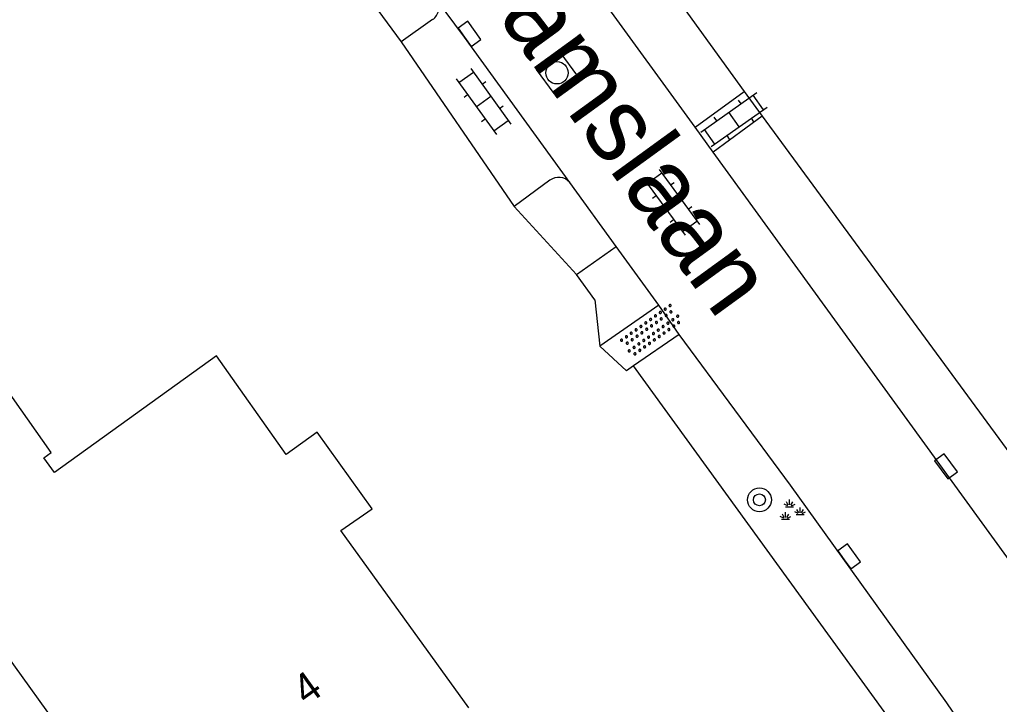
# Model space of a CAD drawing. Extents: x 136000 to 138005, y 398500 to 400500.
# Drawn here: x 137882.54 to 137915.41, y 398783.52 to 398806.52 of the extents above; entities that cross this region are included whole.
import ezdxf

# ---------------------------------------------------------------- set-up
doc = ezdxf.new("R2010")
doc.units = 0
for name, color, linetype in [('gg-afsc-erfafscheiding', 7, 'Continuous'), ('gg-anno-huisnummerreeks BGT', 7, 'Continuous'), ('gg-anno-openbare ruimte label', 7, 'Continuous'), ('gg-bbg-gedigitaliseerde bebouwing', 7, 'Continuous'), ('gg-bbg-hoofdgebouw', 7, 'Continuous'), ('gg-knt-verharding', 7, 'Continuous'), ('gt-grn-vlakafsluiter', 7, 'Continuous'), ('gt-symb-boom', 7, 'Continuous'), ('gt-symb-groenvak', 7, 'Continuous'), ('gt-symb-klinker verharding', 7, 'Continuous'), ('gt-symb-kolk', 7, 'Continuous'), ('gt-symb-overige verharding', 7, 'Continuous'), ('gt-symb-rioolschacht', 7, 'Continuous')]:
    doc.layers.add(name, color=color, linetype=linetype)

# ---------------------------------------------------------------- blocks, each defined once
blk = doc.blocks.new('gt0-KL1')
at = {"layer": 'gt-symb-klinker verharding'}
for p, q in [((-0.5, 0.3), (-0.5, 0.45)), ((0.5, 0.3), (0.5, 0.45)), ((-1.15, 0.3), (1.15, 0.3)), ((-1, -0.3), (-1, 0.3)), ((0, -0.3), (0, 0.3)), ((1, -0.3), (1, 0.3)), ((-1.15, -0.3), (1.15, -0.3)), ((-0.5, -0.45), (-0.5, -0.3)), ((0.5, -0.45), (0.5, -0.3))]:
    blk.add_line(p, q, dxfattribs=at)
blk = doc.blocks.new('gt0-BOOM')
at = {"layer": 'gt-symb-boom'}
for radius in [0.4, 0.2]:
    blk.add_circle((0, 0), radius, dxfattribs=at)
blk = doc.blocks.new('gt0-GRVAK')
at = {"layer": 'gt-symb-groenvak'}
for p, q in [((-0.047, 0.214), (-0.047, 0.393)), ((-0.11, 0.189), (-0.228, 0.24)), ((-0.182, 0.153), (0.088, 0.153)), ((-0.091, 0.211), (-0.156, 0.322)), ((-0.004, 0.211), (0.061, 0.322)), ((0.015, 0.189), (0.133, 0.24)), ((0.262, -0.052), (0.197, 0.059)), ((0.305, -0.049), (0.305, 0.13)), ((0.349, -0.052), (0.414, 0.059)), ((-0.245, -0.228), (-0.363, -0.177)), ((-0.318, -0.264), (-0.047, -0.264)), ((-0.226, -0.206), (-0.291, -0.095)), ((-0.183, -0.203), (-0.183, -0.024)), ((-0.139, -0.206), (-0.074, -0.095)), ((-0.12, -0.228), (-0.002, -0.177)), ((0.243, -0.074), (0.125, -0.023)), ((0.17, -0.11), (0.441, -0.11)), ((0.368, -0.074), (0.486, -0.023))]:
    blk.add_line(p, q, dxfattribs=at)
blk = doc.blocks.new('gt0-KOLK')
at = {"layer": 'gt-symb-kolk'}
blk.add_lwpolyline([(0, 0), (0.375, 0), (0.375, 0.4), (-0.375, 0.4), (-0.375, 0), (0, 0)], dxfattribs=at)
blk = doc.blocks.new('gt0-OVH')
at = {"layer": 'gt-symb-overige verharding'}
for points in [[(-0.972, 0.298), (-0.967, 0.308), (-0.965, 0.319), (-0.966, 0.33), (-0.971, 0.34), (-0.978, 0.348), (-0.988, 0.353), (-0.999, 0.355), (-1.01, 0.354), (-1.02, 0.349), (-1.028, 0.342), (-1.033, 0.332), (-1.035, 0.321), (-1.034, 0.31), (-1.029, 0.3), (-1.022, 0.292), (-1.012, 0.287), (-1.001, 0.285), (-0.99, 0.286), (-0.98, 0.291)], [(-0.772, 0.298), (-0.767, 0.308), (-0.765, 0.319), (-0.766, 0.33), (-0.771, 0.34), (-0.778, 0.348), (-0.788, 0.353), (-0.799, 0.355), (-0.81, 0.354), (-0.82, 0.349), (-0.828, 0.342), (-0.833, 0.332), (-0.835, 0.321), (-0.834, 0.31), (-0.829, 0.3), (-0.822, 0.292), (-0.812, 0.287), (-0.801, 0.285), (-0.79, 0.286), (-0.78, 0.291)], [(-0.572, 0.298), (-0.567, 0.308), (-0.565, 0.319), (-0.566, 0.33), (-0.571, 0.34), (-0.578, 0.348), (-0.588, 0.353), (-0.599, 0.355), (-0.61, 0.354), (-0.62, 0.349), (-0.628, 0.342), (-0.633, 0.332), (-0.635, 0.321), (-0.634, 0.31), (-0.629, 0.3), (-0.622, 0.292), (-0.612, 0.287), (-0.601, 0.285), (-0.59, 0.286), (-0.58, 0.291)], [(-0.372, 0.298), (-0.367, 0.308), (-0.365, 0.319), (-0.366, 0.33), (-0.371, 0.34), (-0.378, 0.348), (-0.388, 0.353), (-0.399, 0.355), (-0.41, 0.354), (-0.42, 0.349), (-0.428, 0.342), (-0.433, 0.332), (-0.435, 0.321), (-0.434, 0.31), (-0.429, 0.3), (-0.422, 0.292), (-0.412, 0.287), (-0.401, 0.285), (-0.39, 0.286), (-0.38, 0.291)], [(-0.172, 0.298), (-0.167, 0.308), (-0.165, 0.319), (-0.166, 0.33), (-0.171, 0.34), (-0.178, 0.348), (-0.188, 0.353), (-0.199, 0.355), (-0.21, 0.354), (-0.22, 0.349), (-0.228, 0.342), (-0.233, 0.332), (-0.235, 0.321), (-0.234, 0.31), (-0.229, 0.3), (-0.222, 0.292), (-0.212, 0.287), (-0.201, 0.285), (-0.19, 0.286), (-0.18, 0.291)], [(0.028, 0.298), (0.033, 0.308), (0.035, 0.319), (0.034, 0.33), (0.029, 0.34), (0.022, 0.348), (0.012, 0.353), (0.001, 0.355), (-0.01, 0.354), (-0.02, 0.349), (-0.028, 0.342), (-0.033, 0.332), (-0.035, 0.321), (-0.034, 0.31), (-0.029, 0.3), (-0.022, 0.292), (-0.012, 0.287), (-0.001, 0.285), (0.01, 0.286), (0.02, 0.291)], [(0.228, 0.298), (0.233, 0.308), (0.235, 0.319), (0.234, 0.33), (0.229, 0.34), (0.222, 0.348), (0.212, 0.353), (0.201, 0.355), (0.19, 0.354), (0.18, 0.349), (0.172, 0.342), (0.167, 0.332), (0.165, 0.321), (0.166, 0.31), (0.171, 0.3), (0.178, 0.292), (0.188, 0.287), (0.199, 0.285), (0.21, 0.286), (0.22, 0.291)], [(0.428, 0.298), (0.433, 0.308), (0.435, 0.319), (0.434, 0.33), (0.429, 0.34), (0.422, 0.348), (0.412, 0.353), (0.401, 0.355), (0.39, 0.354), (0.38, 0.349), (0.372, 0.342), (0.367, 0.332), (0.365, 0.321), (0.366, 0.31), (0.371, 0.3), (0.378, 0.292), (0.388, 0.287), (0.399, 0.285), (0.41, 0.286), (0.42, 0.291)], [(0.628, 0.298), (0.633, 0.308), (0.635, 0.319), (0.634, 0.33), (0.629, 0.34), (0.622, 0.348), (0.612, 0.353), (0.601, 0.355), (0.59, 0.354), (0.58, 0.349), (0.572, 0.342), (0.567, 0.332), (0.565, 0.321), (0.566, 0.31), (0.571, 0.3), (0.578, 0.292), (0.588, 0.287), (0.599, 0.285), (0.61, 0.286), (0.62, 0.291)], [(0.828, 0.298), (0.833, 0.308), (0.835, 0.319), (0.834, 0.33), (0.829, 0.34), (0.822, 0.348), (0.812, 0.353), (0.801, 0.355), (0.79, 0.354), (0.78, 0.349), (0.772, 0.342), (0.767, 0.332), (0.765, 0.321), (0.766, 0.31), (0.771, 0.3), (0.778, 0.292), (0.788, 0.287), (0.799, 0.285), (0.81, 0.286), (0.82, 0.291)], [(1.028, 0.298), (1.033, 0.308), (1.035, 0.319), (1.034, 0.33), (1.029, 0.34), (1.022, 0.348), (1.012, 0.353), (1.001, 0.355), (0.99, 0.354), (0.98, 0.349), (0.972, 0.342), (0.967, 0.332), (0.965, 0.321), (0.966, 0.31), (0.971, 0.3), (0.978, 0.292), (0.988, 0.287), (0.999, 0.285), (1.01, 0.286), (1.02, 0.291)], [(-0.872, 0.106), (-0.867, 0.116), (-0.865, 0.126), (-0.866, 0.137), (-0.871, 0.147), (-0.878, 0.156), (-0.888, 0.161), (-0.899, 0.163), (-0.91, 0.162), (-0.92, 0.157), (-0.928, 0.15), (-0.933, 0.14), (-0.935, 0.129), (-0.934, 0.118), (-0.929, 0.108), (-0.922, 0.1), (-0.912, 0.095), (-0.901, 0.092), (-0.89, 0.094), (-0.88, 0.098)], [(-0.672, 0.106), (-0.667, 0.116), (-0.665, 0.126), (-0.666, 0.137), (-0.671, 0.147), (-0.678, 0.156), (-0.688, 0.161), (-0.699, 0.163), (-0.71, 0.162), (-0.72, 0.157), (-0.728, 0.15), (-0.733, 0.14), (-0.735, 0.129), (-0.734, 0.118), (-0.729, 0.108), (-0.722, 0.1), (-0.712, 0.095), (-0.701, 0.092), (-0.69, 0.094), (-0.68, 0.098)], [(-0.472, 0.106), (-0.467, 0.116), (-0.465, 0.126), (-0.466, 0.137), (-0.471, 0.147), (-0.478, 0.156), (-0.488, 0.161), (-0.499, 0.163), (-0.51, 0.162), (-0.52, 0.157), (-0.528, 0.15), (-0.533, 0.14), (-0.535, 0.129), (-0.534, 0.118), (-0.529, 0.108), (-0.522, 0.1), (-0.512, 0.095), (-0.501, 0.092), (-0.49, 0.094), (-0.48, 0.098)], [(-0.272, 0.106), (-0.267, 0.116), (-0.265, 0.126), (-0.266, 0.137), (-0.271, 0.147), (-0.278, 0.156), (-0.288, 0.161), (-0.299, 0.163), (-0.31, 0.162), (-0.32, 0.157), (-0.328, 0.15), (-0.333, 0.14), (-0.335, 0.129), (-0.334, 0.118), (-0.329, 0.108), (-0.322, 0.1), (-0.312, 0.095), (-0.301, 0.092), (-0.29, 0.094), (-0.28, 0.098)], [(-0.072, 0.106), (-0.067, 0.116), (-0.065, 0.126), (-0.066, 0.137), (-0.071, 0.147), (-0.078, 0.156), (-0.088, 0.161), (-0.099, 0.163), (-0.11, 0.162), (-0.12, 0.157), (-0.128, 0.15), (-0.133, 0.14), (-0.135, 0.129), (-0.134, 0.118), (-0.129, 0.108), (-0.122, 0.1), (-0.112, 0.095), (-0.101, 0.092), (-0.09, 0.094), (-0.08, 0.098)], [(0.128, 0.106), (0.133, 0.116), (0.135, 0.126), (0.134, 0.137), (0.129, 0.147), (0.122, 0.156), (0.112, 0.161), (0.101, 0.163), (0.09, 0.162), (0.08, 0.157), (0.072, 0.15), (0.067, 0.14), (0.065, 0.129), (0.066, 0.118), (0.071, 0.108), (0.078, 0.1), (0.088, 0.095), (0.099, 0.092), (0.11, 0.094), (0.12, 0.098)], [(0.328, 0.106), (0.333, 0.116), (0.335, 0.126), (0.334, 0.137), (0.329, 0.147), (0.322, 0.156), (0.312, 0.161), (0.301, 0.163), (0.29, 0.162), (0.28, 0.157), (0.272, 0.15), (0.267, 0.14), (0.265, 0.129), (0.266, 0.118), (0.271, 0.108), (0.278, 0.1), (0.288, 0.095), (0.299, 0.092), (0.31, 0.094), (0.32, 0.098)], [(0.528, 0.106), (0.533, 0.116), (0.535, 0.126), (0.534, 0.137), (0.529, 0.147), (0.522, 0.156), (0.512, 0.161), (0.501, 0.163), (0.49, 0.162), (0.48, 0.157), (0.472, 0.15), (0.467, 0.14), (0.465, 0.129), (0.466, 0.118), (0.471, 0.108), (0.478, 0.1), (0.488, 0.095), (0.499, 0.092), (0.51, 0.094), (0.52, 0.098)], [(0.728, 0.106), (0.733, 0.116), (0.735, 0.126), (0.734, 0.137), (0.729, 0.147), (0.722, 0.156), (0.712, 0.161), (0.701, 0.163), (0.69, 0.162), (0.68, 0.157), (0.672, 0.15), (0.667, 0.14), (0.665, 0.129), (0.666, 0.118), (0.671, 0.108), (0.678, 0.1), (0.688, 0.095), (0.699, 0.092), (0.71, 0.094), (0.72, 0.098)], [(0.928, 0.106), (0.933, 0.116), (0.935, 0.126), (0.934, 0.137), (0.929, 0.147), (0.922, 0.156), (0.912, 0.161), (0.901, 0.163), (0.89, 0.162), (0.88, 0.157), (0.872, 0.15), (0.867, 0.14), (0.865, 0.129), (0.866, 0.118), (0.871, 0.108), (0.878, 0.1), (0.888, 0.095), (0.899, 0.092), (0.91, 0.094), (0.92, 0.098)], [(-0.972, -0.142), (-0.967, -0.132), (-0.965, -0.121), (-0.966, -0.11), (-0.971, -0.1), (-0.978, -0.092), (-0.988, -0.087), (-0.999, -0.085), (-1.01, -0.086), (-1.02, -0.091), (-1.028, -0.098), (-1.033, -0.108), (-1.035, -0.119), (-1.034, -0.13), (-1.029, -0.14), (-1.022, -0.148), (-1.012, -0.153), (-1.001, -0.155), (-0.99, -0.154), (-0.98, -0.149)], [(-0.872, -0.334), (-0.867, -0.324), (-0.865, -0.314), (-0.866, -0.303), (-0.871, -0.293), (-0.878, -0.284), (-0.888, -0.279), (-0.899, -0.277), (-0.91, -0.278), (-0.92, -0.283), (-0.928, -0.29), (-0.933, -0.3), (-0.935, -0.311), (-0.934, -0.322), (-0.929, -0.332), (-0.922, -0.34), (-0.912, -0.345), (-0.901, -0.348), (-0.89, -0.346), (-0.88, -0.342)], [(-0.772, -0.142), (-0.767, -0.132), (-0.765, -0.121), (-0.766, -0.11), (-0.771, -0.1), (-0.778, -0.092), (-0.788, -0.087), (-0.799, -0.085), (-0.81, -0.086), (-0.82, -0.091), (-0.828, -0.098), (-0.833, -0.108), (-0.835, -0.119), (-0.834, -0.13), (-0.829, -0.14), (-0.822, -0.148), (-0.812, -0.153), (-0.801, -0.155), (-0.79, -0.154), (-0.78, -0.149)], [(-0.672, -0.334), (-0.667, -0.324), (-0.665, -0.314), (-0.666, -0.303), (-0.671, -0.293), (-0.678, -0.284), (-0.688, -0.279), (-0.699, -0.277), (-0.71, -0.278), (-0.72, -0.283), (-0.728, -0.29), (-0.733, -0.3), (-0.735, -0.311), (-0.734, -0.322), (-0.729, -0.332), (-0.722, -0.34), (-0.712, -0.345), (-0.701, -0.348), (-0.69, -0.346), (-0.68, -0.342)], [(-0.572, -0.142), (-0.567, -0.132), (-0.565, -0.121), (-0.566, -0.11), (-0.571, -0.1), (-0.578, -0.092), (-0.588, -0.087), (-0.599, -0.085), (-0.61, -0.086), (-0.62, -0.091), (-0.628, -0.098), (-0.633, -0.108), (-0.635, -0.119), (-0.634, -0.13), (-0.629, -0.14), (-0.622, -0.148), (-0.612, -0.153), (-0.601, -0.155), (-0.59, -0.154), (-0.58, -0.149)], [(-0.472, -0.334), (-0.467, -0.324), (-0.465, -0.314), (-0.466, -0.303), (-0.471, -0.293), (-0.478, -0.284), (-0.488, -0.279), (-0.499, -0.277), (-0.51, -0.278), (-0.52, -0.283), (-0.528, -0.29), (-0.533, -0.3), (-0.535, -0.311), (-0.534, -0.322), (-0.529, -0.332), (-0.522, -0.34), (-0.512, -0.345), (-0.501, -0.348), (-0.49, -0.346), (-0.48, -0.342)], [(-0.372, -0.142), (-0.367, -0.132), (-0.365, -0.121), (-0.366, -0.11), (-0.371, -0.1), (-0.378, -0.092), (-0.388, -0.087), (-0.399, -0.085), (-0.41, -0.086), (-0.42, -0.091), (-0.428, -0.098), (-0.433, -0.108), (-0.435, -0.119), (-0.434, -0.13), (-0.429, -0.14), (-0.422, -0.148), (-0.412, -0.153), (-0.401, -0.155), (-0.39, -0.154), (-0.38, -0.149)], [(-0.272, -0.334), (-0.267, -0.324), (-0.265, -0.314), (-0.266, -0.303), (-0.271, -0.293), (-0.278, -0.284), (-0.288, -0.279), (-0.299, -0.277), (-0.31, -0.278), (-0.32, -0.283), (-0.328, -0.29), (-0.333, -0.3), (-0.335, -0.311), (-0.334, -0.322), (-0.329, -0.332), (-0.322, -0.34), (-0.312, -0.345), (-0.301, -0.348), (-0.29, -0.346), (-0.28, -0.342)], [(-0.172, -0.142), (-0.167, -0.132), (-0.165, -0.121), (-0.166, -0.11), (-0.171, -0.1), (-0.178, -0.092), (-0.188, -0.087), (-0.199, -0.085), (-0.21, -0.086), (-0.22, -0.091), (-0.228, -0.098), (-0.233, -0.108), (-0.235, -0.119), (-0.234, -0.13), (-0.229, -0.14), (-0.222, -0.148), (-0.212, -0.153), (-0.201, -0.155), (-0.19, -0.154), (-0.18, -0.149)], [(-0.072, -0.334), (-0.067, -0.324), (-0.065, -0.314), (-0.066, -0.303), (-0.071, -0.293), (-0.078, -0.284), (-0.088, -0.279), (-0.099, -0.277), (-0.11, -0.278), (-0.12, -0.283), (-0.128, -0.29), (-0.133, -0.3), (-0.135, -0.311), (-0.134, -0.322), (-0.129, -0.332), (-0.122, -0.34), (-0.112, -0.345), (-0.101, -0.348), (-0.09, -0.346), (-0.08, -0.342)], [(0.028, -0.142), (0.033, -0.132), (0.035, -0.121), (0.034, -0.11), (0.029, -0.1), (0.022, -0.092), (0.012, -0.087), (0.001, -0.085), (-0.01, -0.086), (-0.02, -0.091), (-0.028, -0.098), (-0.033, -0.108), (-0.035, -0.119), (-0.034, -0.13), (-0.029, -0.14), (-0.022, -0.148), (-0.012, -0.153), (-0.001, -0.155), (0.01, -0.154), (0.02, -0.149)], [(0.128, -0.334), (0.133, -0.324), (0.135, -0.314), (0.134, -0.303), (0.129, -0.293), (0.122, -0.284), (0.112, -0.279), (0.101, -0.277), (0.09, -0.278), (0.08, -0.283), (0.072, -0.29), (0.067, -0.3), (0.065, -0.311), (0.066, -0.322), (0.071, -0.332), (0.078, -0.34), (0.088, -0.345), (0.099, -0.348), (0.11, -0.346), (0.12, -0.342)], [(0.228, -0.142), (0.233, -0.132), (0.235, -0.121), (0.234, -0.11), (0.229, -0.1), (0.222, -0.092), (0.212, -0.087), (0.201, -0.085), (0.19, -0.086), (0.18, -0.091), (0.172, -0.098), (0.167, -0.108), (0.165, -0.119), (0.166, -0.13), (0.171, -0.14), (0.178, -0.148), (0.188, -0.153), (0.199, -0.155), (0.21, -0.154), (0.22, -0.149)], [(0.328, -0.334), (0.333, -0.324), (0.335, -0.314), (0.334, -0.303), (0.329, -0.293), (0.322, -0.284), (0.312, -0.279), (0.301, -0.277), (0.29, -0.278), (0.28, -0.283), (0.272, -0.29), (0.267, -0.3), (0.265, -0.311), (0.266, -0.322), (0.271, -0.332), (0.278, -0.34), (0.288, -0.345), (0.299, -0.348), (0.31, -0.346), (0.32, -0.342)], [(0.428, -0.142), (0.433, -0.132), (0.435, -0.121), (0.434, -0.11), (0.429, -0.1), (0.422, -0.092), (0.412, -0.087), (0.401, -0.085), (0.39, -0.086), (0.38, -0.091), (0.372, -0.098), (0.367, -0.108), (0.365, -0.119), (0.366, -0.13), (0.371, -0.14), (0.378, -0.148), (0.388, -0.153), (0.399, -0.155), (0.41, -0.154), (0.42, -0.149)], [(0.528, -0.334), (0.533, -0.324), (0.535, -0.314), (0.534, -0.303), (0.529, -0.293), (0.522, -0.284), (0.512, -0.279), (0.501, -0.277), (0.49, -0.278), (0.48, -0.283), (0.472, -0.29), (0.467, -0.3), (0.465, -0.311), (0.466, -0.322), (0.471, -0.332), (0.478, -0.34), (0.488, -0.345), (0.499, -0.348), (0.51, -0.346), (0.52, -0.342)], [(0.628, -0.142), (0.633, -0.132), (0.635, -0.121), (0.634, -0.11), (0.629, -0.1), (0.622, -0.092), (0.612, -0.087), (0.601, -0.085), (0.59, -0.086), (0.58, -0.091), (0.572, -0.098), (0.567, -0.108), (0.565, -0.119), (0.566, -0.13), (0.571, -0.14), (0.578, -0.148), (0.588, -0.153), (0.599, -0.155), (0.61, -0.154), (0.62, -0.149)], [(0.728, -0.334), (0.733, -0.324), (0.735, -0.314), (0.734, -0.303), (0.729, -0.293), (0.722, -0.284), (0.712, -0.279), (0.701, -0.277), (0.69, -0.278), (0.68, -0.283), (0.672, -0.29), (0.667, -0.3), (0.665, -0.311), (0.666, -0.322), (0.671, -0.332), (0.678, -0.34), (0.688, -0.345), (0.699, -0.348), (0.71, -0.346), (0.72, -0.342)], [(0.828, -0.142), (0.833, -0.132), (0.835, -0.121), (0.834, -0.11), (0.829, -0.1), (0.822, -0.092), (0.812, -0.087), (0.801, -0.085), (0.79, -0.086), (0.78, -0.091), (0.772, -0.098), (0.767, -0.108), (0.765, -0.119), (0.766, -0.13), (0.771, -0.14), (0.778, -0.148), (0.788, -0.153), (0.799, -0.155), (0.81, -0.154), (0.82, -0.149)], [(0.928, -0.334), (0.933, -0.324), (0.935, -0.314), (0.934, -0.303), (0.929, -0.293), (0.922, -0.284), (0.912, -0.279), (0.901, -0.277), (0.89, -0.278), (0.88, -0.283), (0.872, -0.29), (0.867, -0.3), (0.865, -0.311), (0.866, -0.322), (0.871, -0.332), (0.878, -0.34), (0.888, -0.345), (0.899, -0.348), (0.91, -0.346), (0.92, -0.342)], [(1.028, -0.142), (1.033, -0.132), (1.035, -0.121), (1.034, -0.11), (1.029, -0.1), (1.022, -0.092), (1.012, -0.087), (1.001, -0.085), (0.99, -0.086), (0.98, -0.091), (0.972, -0.098), (0.967, -0.108), (0.965, -0.119), (0.966, -0.13), (0.971, -0.14), (0.978, -0.148), (0.988, -0.153), (0.999, -0.155), (1.01, -0.154), (1.02, -0.149)]]:
    blk.add_lwpolyline(points, close=True, dxfattribs=at)
blk = doc.blocks.new('gt0-RS')
at = {"layer": 'gt-symb-rioolschacht'}
blk.add_lwpolyline([(-0.5, -0.5), (0.5, -0.5), (0.5, 0.5), (-0.5, 0.5)], close=True, dxfattribs=at)
blk.add_circle((0, 0), 0.375, dxfattribs=at)

msp = doc.modelspace()

# ---------------------------------------------------------------- linework, layer by layer
at = {"layer": 'gg-afsc-erfafscheiding'}
for p, q in [((137891.987, 398824.709), (137906.852, 398804.097)), ((137906.852, 398804.097), (137907.455, 398803.274)), ((137907.455, 398803.274), (137920.911, 398784.911)), ((137901.835, 398797.099), (137901.226, 398797.954))]:
    msp.add_line(p, q, dxfattribs=at)
at = {"layer": 'gg-bbg-gedigitaliseerde bebouwing'}
msp.add_lwpolyline([(137881.128, 398795.482), (137868.039, 398786.474), (137870.728, 398782.73), (137879.384, 398788.948), (137886.67, 398778.805), (137889.995, 398781.199)], dxfattribs=at)
at = {"layer": 'gg-bbg-hoofdgebouw'}
for p, q in [((137883.594, 398791.976), (137881.128, 398795.482)), ((137883.354, 398791.803), (137883.594, 398791.976))]:
    msp.add_line(p, q, dxfattribs=at)
for points in [[(137892.518, 398792.663), (137891.479, 398791.915), (137889.148, 398795.223), (137883.71, 398791.308), (137883.354, 398791.803)], [(137897.61, 398783.4), (137893.32, 398789.36), (137894.37, 398790.09), (137892.518, 398792.663)]]:
    msp.add_lwpolyline(points, dxfattribs=at)
at = {"layer": 'gg-knt-verharding'}
for p, q in [((137905.2, 398802.905), (137890.286, 398823.483)), ((137896.394, 398806.516), (137895.338, 398805.77)), ((137905.2, 398802.905), (137906.852, 398804.097)), ((137907.455, 398803.274), (137905.807, 398802.067)), ((137905.807, 398802.067), (137905.2, 398802.905)), ((137919.167, 398783.633), (137905.807, 398802.067)), ((137900.333, 398801.122), (137899.131, 398800.236)), ((137902.554, 398798.899), (137900.995, 398801.049)), ((137901.226, 398797.954), (137902.554, 398798.899)), ((137903.985, 398796.925), (137902.554, 398798.899)), ((137903.985, 398796.925), (137902.011, 398795.552)), ((137904.672, 398795.944), (137903.985, 398796.925)), ((137904.672, 398795.944), (137903.136, 398794.884)), ((137903.136, 398794.884), (137902.896, 398794.718))]:
    msp.add_line(p, q, dxfattribs=at)
for points in [[(137900.995, 398801.049), (137897.47, 398805.921), (137896.522, 398807.202)], [(137914.514, 398782.303), (137913.647, 398783.572), (137908.4, 398790.878), (137904.672, 398795.944)]]:
    msp.add_lwpolyline(points, dxfattribs=at)
for centre, radius, start, end in [((137896.118, 398806.922), 0.491, 304.151, 34.7106), ((137900.625, 398800.734), 0.485, 40.3896, 127.025)]:
    msp.add_arc(centre, radius, start, end, dxfattribs=at)
at = {"layer": 'gt-grn-vlakafsluiter'}
for p, q in [((137883.96, 398821.341), (137895.338, 398805.77)), ((137895.338, 398805.77), (137899.131, 398800.236)), ((137899.131, 398800.236), (137901.226, 398797.954)), ((137901.835, 398797.099), (137902.011, 398795.552)), ((137902.011, 398795.552), (137902.896, 398794.718))]:
    msp.add_line(p, q, dxfattribs=at)
msp.add_lwpolyline([(137912.488, 398781.928), (137912.195, 398782.379), (137903.136, 398794.884)], dxfattribs=at)

# ---------------------------------------------------------------- block references
at = {"layer": 'gt-symb-boom'}
msp.add_blockref('gt0-BOOM', (137907.362, 398790.387), dxfattribs=at)
at = {"layer": 'gt-symb-groenvak'}
msp.add_blockref('gt0-GRVAK', (137908.422, 398790.002), dxfattribs=at)
at = {"layer": 'gt-symb-klinker verharding'}
for p, rotation in [((137898.106, 398803.764), -54.275865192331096), ((137906.509, 398803.158), 35.2644302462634), ((137904.43, 398800.38), -53.829355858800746)]:
    msp.add_blockref('gt0-KL1', p, dxfattribs=dict(at, rotation=rotation))
at = {"layer": 'gt-symb-kolk'}
for p, rotation in [((137897.47, 398805.921), -54.11588683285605), ((137913.461, 398791.391), -53.829355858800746), ((137910.21, 398788.372), -54.4023685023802)]:
    msp.add_blockref('gt0-KOLK', p, dxfattribs=dict(at, rotation=rotation))
at = {"layer": 'gt-symb-overige verharding', "rotation": 35.59763149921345}
msp.add_blockref('gt0-OVH', (137903.735, 398796.069), dxfattribs=at)
at = {"layer": 'gt-symb-rioolschacht', "rotation": -53.829355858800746}
msp.add_blockref('gt0-RS', (137900.569, 398804.728), dxfattribs=at)

# ---------------------------------------------------------------- texts
at = {"layer": 'gg-anno-huisnummerreeks BGT'}
msp.add_text('4', height=1, rotation=35.7, dxfattribs=at).set_placement((137892.161, 398783.458))
at = {"layer": 'gg-anno-openbare ruimte label'}
msp.add_text('Burgemeester Adamslaan', height=2.5, rotation=306, dxfattribs=at).set_placement((137883.279, 398827.657))

doc.saveas('drawing.dxf')
